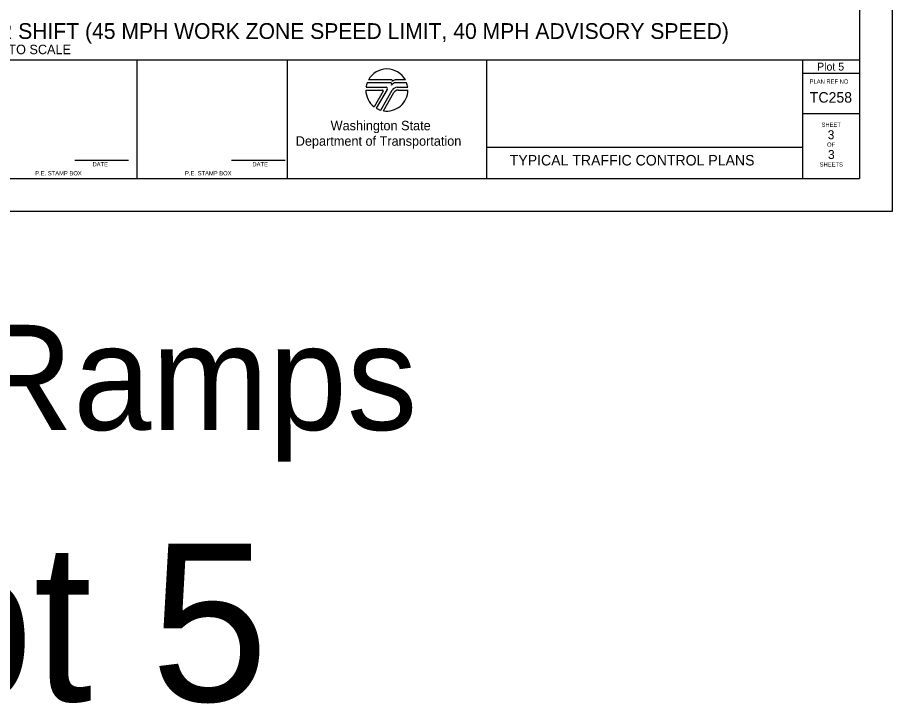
# Model space of a CAD drawing. Extents: x 99999 to 100116, y 99995 to 100013.
# Drawn here: x 100087.75 to 100096.06, y 99995.01 to 100001.53 of the extents above; entities that cross this region are included whole.
import ezdxf

# ---------------------------------------------------------------- set-up
doc = ezdxf.new("R2010")
doc.units = 0
for name, color, linetype in [('SH_DE_DetailHeading1Text', 7, 'Continuous'), ('SH_GI_PlotLimits', 7, 'Continuous'), ('SH_GI_SheetBorder', 7, 'Continuous'), ('SH_GI_SheetLocationText', 7, 'Continuous'), ('SH_GI_SheetTextInCells', 7, 'Continuous'), ('SH_GI_TitleBlockText', 7, 'Continuous'), ('SH_GI_WSDOTLogo', 7, 'Continuous')]:
    doc.layers.add(name, color=color, linetype=linetype)

msp = doc.modelspace()

# ---------------------------------------------------------------- linework, layer by layer
at = {"layer": 'SH_GI_PlotLimits'}
msp.add_lwpolyline([(100079.0625, 99999.6875), (100096.0625, 99999.6875), (100096.0625, 100010.6875), (100079.0625, 100010.6875)], close=True, dxfattribs=at)
at = {"layer": 'SH_GI_SheetBorder'}
for p, q in [((100095.75, 100010.375), (100095.75, 100000)), ((100080, 100001.1259), (100095.75, 100001.1259)), ((100088.8828, 100000), (100088.8828, 100001.1259)), ((100090.3089, 100001.1259), (100090.3089, 100000)), ((100092.2055, 100001.1259), (100092.2055, 100000)), ((100095.2079, 100001.1259), (100095.2079, 100000)), ((100095.2079, 100001.0008), (100095.75, 100001.0008)), ((100095.2079, 100000.6176), (100095.75, 100000.6176)), ((100092.2055, 100000.2955), (100095.2079, 100000.2955)), ((100088.2903, 100000.1733), (100088.802, 100000.1733)), ((100089.7797, 100000.1733), (100090.2914, 100000.1733)), ((100080, 100000), (100095.75, 100000))]:
    msp.add_line(p, q, dxfattribs=at)
at = {"layer": 'SH_GI_WSDOTLogo'}
for p, q in [((100091.2894, 100000.9094), (100091.0697, 100000.9094)), ((100091.303, 100000.9354), (100091.0815, 100000.9354)), ((100091.433, 100000.9354), (100091.3351, 100000.9354)), ((100091.343, 100000.9094), (100091.3429, 100000.9094)), ((100091.4448, 100000.9094), (100091.343, 100000.9094)), ((100091.0572, 100000.84), (100091.2148, 100000.84)), ((100091.059, 100000.8661), (100091.2496, 100000.8661)), ((100091.222, 100000.8277), (100091.1364, 100000.6807)), ((100091.261, 100000.8464), (100091.1567, 100000.6672)), ((100091.1989, 100000.6487), (100091.3089, 100000.839)), ((100091.2244, 100000.6428), (100091.3242, 100000.8156)), ((100091.3558, 100000.8661), (100091.4555, 100000.8661)), ((100091.3655, 100000.8394), (100091.4572, 100000.8394))]:
    msp.add_line(p, q, dxfattribs=at)
for centre, radius, start, end in [((100091.2572, 100000.84), 0.2, 28.47865, 151.53204), ((100091.2572, 100000.84), 0.2, 159.69598, 172.50569), ((100091.2894, 100000.8946), 0.0148, 327.8418, 89.99855), ((100091.3429, 100000.861), 0.0484, 89.99529, 147.82376), ((100091.303, 100000.9263), 0.00903, 329.87418, 90.00328), ((100091.3352, 100000.9066), 0.0287, 90.00721, 148.16763), ((100091.2572, 100000.84), 0.2, 7.49431, 20.29406), ((100091.2572, 100000.84), 0.2, 179.99864, 232.84327), ((100091.2149, 100000.8318), 0.0082, 329.74356, 90), ((100091.2572, 100000.84), 0.2, 260.54554, 359.80857), ((100091.2497, 100000.853), 0.0131, 329.76834, 90), ((100091.3558, 100000.8119), 0.0542, 90, 149.99738), ((100091.3654, 100000.7918), 0.0476, 90, 150.05432), ((100091.2572, 100000.84), 0.2, 239.79292, 253.0448)]:
    msp.add_arc(centre, radius, start, end, dxfattribs=at)

# ---------------------------------------------------------------- texts
at = {"layer": 'SH_DE_DetailHeading1Text'}
for s, height, p in [("FREEWAY (2 LANES): SINGLE RIGHT LANE CLOSURE, 9' MAX LEFT SHOULDER SHIFT (45 MPH WORK ZONE SPEED LIMIT, 40 MPH ADVISORY SPEED)", 0.15, (100080.0913, 100001.3259)), ('NOT TO SCALE', 0.09, (100087.3727, 100001.1809))]:
    msp.add_text(s, height=height, rotation=360, dxfattribs=at).set_placement(p)
at = {"layer": 'SH_GI_SheetBorder'}
msp.add_text('PLAN REF NO', height=0.040032, dxfattribs=at).set_placement((100095.2747, 100000.9008))
at = {"layer": 'SH_GI_SheetLocationText'}
for s, height, p in [('Plot 5', 0.075, (100095.346, 100001.025)), ('Left Ramps', 1, (100084.7087, 99997.6071)), ('Plot 5', 1.5, (100085.0007, 99995.0267))]:
    msp.add_text(s, height=height, dxfattribs=at).set_placement(p)
at = {"layer": 'SH_GI_SheetTextInCells'}
for s, height, p in [('Washington State', 0.090072, (100090.7229, 100000.4571)), ('SHEET', 0.04003, (100095.3877, 100000.4896)), ('Department of Transportation', 0.090072, (100090.3916, 100000.3101)), ('OF', 0.04003, (100095.4406, 100000.3008)), ('DATE', 0.04003, (100088.4597, 100000.1141)), ('DATE', 0.04003, (100089.9794, 100000.1141)), ('SHEETS', 0.04003, (100095.3698, 100000.112)), ('P.E. STAMP BOX', 0.040032, (100087.915, 100000.0286)), ('P.E. STAMP BOX', 0.040032, (100089.339, 100000.0286))]:
    msp.add_text(s, height=height, dxfattribs=at).set_placement(p)
at = {"layer": 'SH_GI_TitleBlockText'}
for s, height, p in [('TC258', 0.1, (100095.2767, 100000.72)), ('3', 0.085, (100095.4468, 100000.3723)), ('3', 0.085, (100095.4493, 100000.1843)), ('TYPICAL TRAFFIC CONTROL PLANS', 0.1, (100092.4251, 100000.1224))]:
    msp.add_text(s, height=height, dxfattribs=at).set_placement(p)

doc.saveas('drawing.dxf')
